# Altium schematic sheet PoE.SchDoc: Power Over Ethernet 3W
size A4; Date: 29-OCT-2015; Author: A.B; CompanyName: STMicroelectronics; Organization: MCD/TOOLS/GNB; Address1: 12, Rue Jules HOROWITZ; Address2: 38019 Grenoble; Address3: FRANCE; DocumentNumber: MB1225; Revision: B-01; SheetNumber: 11; SheetTotal: 13; Project: STM32F769I-DISCO
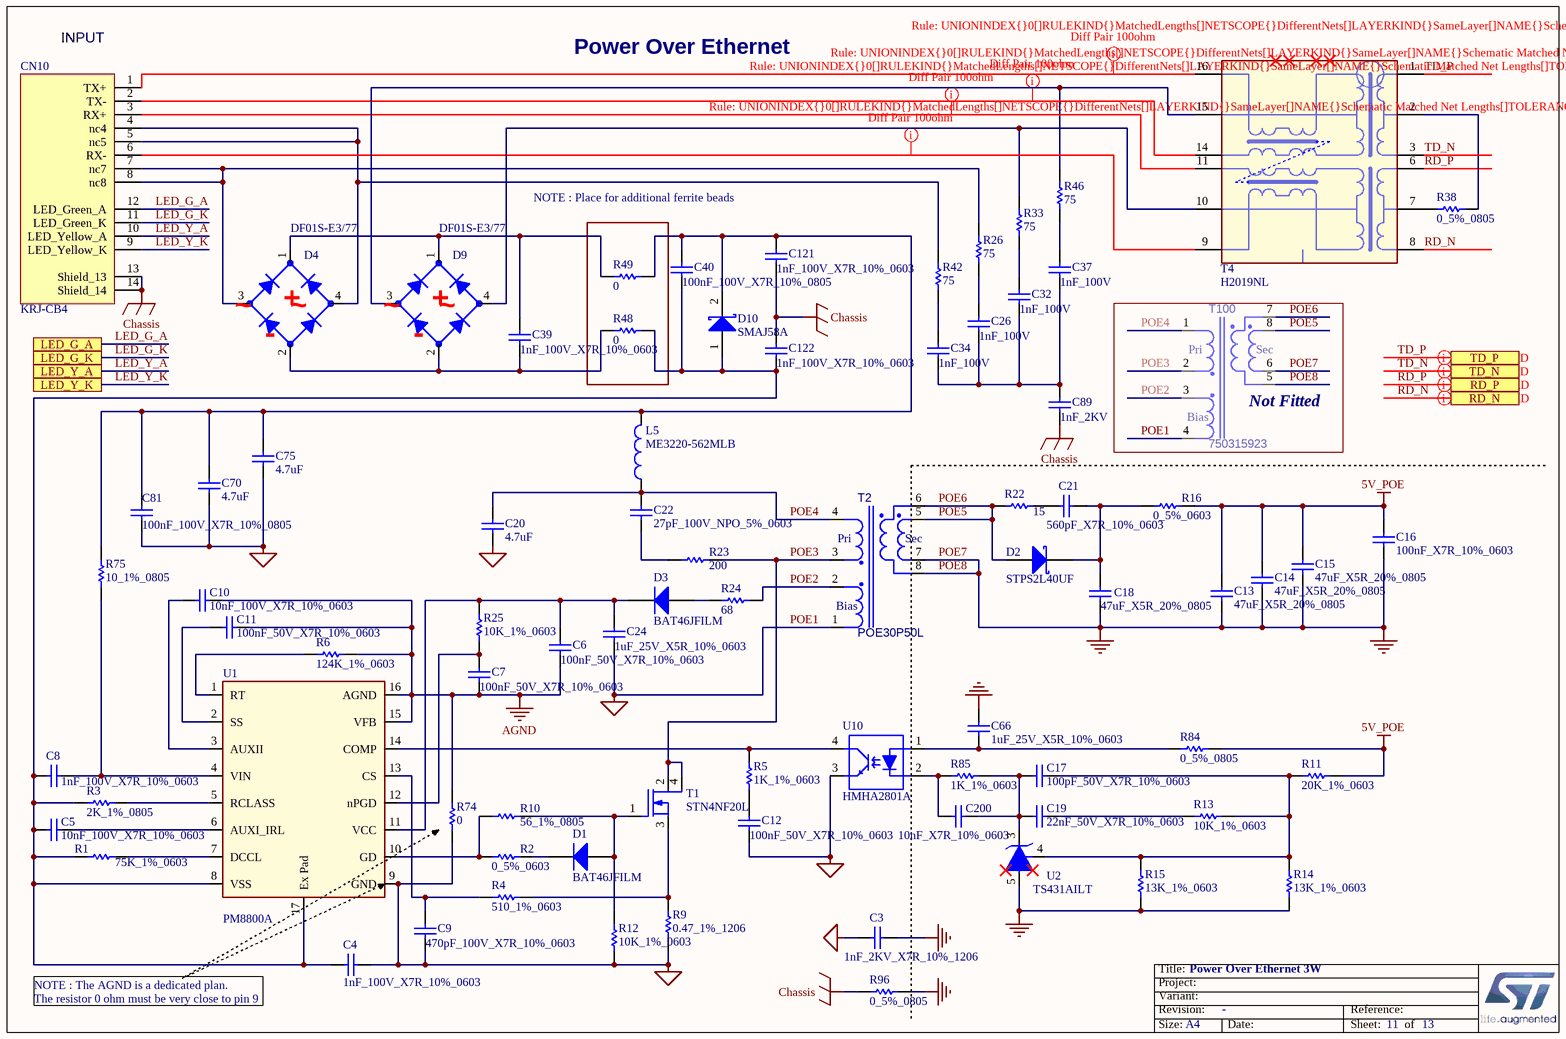
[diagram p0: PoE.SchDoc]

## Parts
C3  1nF_2KV_X7R_10%_1206  [1206C]
C4  1nF_100V_X7R_10%_0603  [0603C]
C5  10nF_100V_X7R_10%_0603  [0603C]
C6  100nF_50V_X7R_10%_0603  [0603C]
C7  100nF_50V_X7R_10%_0603  [0603C]
C8  1nF_100V_X7R_10%_0603  [0603C]
C9  470pF_100V_X7R_10%_0603  [0603C]
C10  10nF_100V_X7R_10%_0603  [0603C]
C11  100nF_50V_X7R_10%_0603  [0603C]
C12  100nF_50V_X7R_10%_0603  [0603C]
C13  47uF_X5R_20%_0805  [0805C]
C14  47uF_X5R_20%_0805  [0805C]
C15  47uF_X5R_20%_0805  [0805C]
C16  100nF_X7R_10%_0603  [0603C]
C17  100pF_50V_X7R_10%_0603  [0603C]
C18  47uF_X5R_20%_0805  [0805C]
C19  22nF_50V_X7R_10%_0603  [0603C]
C20  value 4.7uF  [C1210_H2P5]  (hidden comment: Capacitor)
C21  560pF_X7R_10%_0603  [0603C]
C22  27pF_100V_NPO_5%_0603  [0603C]
C24  1uF_25V_X5R_10%_0603  [0603C]
C26  1nF_100V  [0603C]
C32  1nF_100V  [0603C]
C34  1nF_100V  [0603C]
C37  1nF_100V  [0603C]
C39  1nF_100V_X7R_10%_0603  [0603C]
C40  100nF_100V_X7R_10%_0805  [0805C]
C66  1uF_25V_X5R_10%_0603  [0603C]
C70  value 4.7uF  [C1210_H2P5]  (hidden comment: Capacitor)
C75  value 4.7uF  [C1210_H2P5]  (hidden comment: Capacitor)
C81  100nF_100V_X7R_10%_0805  [0805C]
C89  1nF_2KV  [1206C]
C121  1nF_100V_X7R_10%_0603  [0603C]
C122  1nF_100V_X7R_10%_0603  [0603C]
C200  10nF_X7R_10%_0603  [0603C]
CN10  KRJ-CB4  [RJ45_LED_KRJ-CB4R2GYZNL_EM]
D1  BAT46JFILM  [SOD-323]
D2  STPS2L40UF  [SMB]
D3  BAT46JFILM  [SOD-323]
D4  value DF01S-E3/77  [BRF_VISHAY_DFS_DF01S]
D9  value DF01S-E3/77  [BRF_VISHAY_DFS_DF01S]
D10  SMAJ58A  [SMA]
L5  ME3220-562MLB  [LSM2_3R2X2R8_H2]
R1  75K_1%_0603  [0603R]
R2  0_5%_0603  [0603R-GS]
R3  2K_1%_0805  [0805R]
R4  510_1%_0603  [0603R]
R5  1K_1%_0603  [0603R]
R6  124K_1%_0603  [0603R]
R9  0.47_1%_1206  [1206R]
R10  56_1%_0805  [0805R]
R11  20K_1%_0603  [0603R]
R12  10K_1%_0603  [0603R]
R13  10K_1%_0603  [0603R]
R14  13K_1%_0603  [0603R]
R15  13K_1%_0603  [0603R]
R16  0_5%_0603  [0603R-GS]
R22  15  [0805R]
R23  200  [1206R]
R24  68  [0805R]
R25  10K_1%_0603  [0603R]
R26  75  [0805R]
R33  75  [0805R]
R38  0_5%_0805  [0805R]
R42  75  [0805R]
R46  75  [0805R]
R48  0  [0805R]
R49  0  [0805R]
R74  0  [0603R-GS]
R75  10_1%_0805  [0805R]
R84  0_5%_0805  [0805R]
R85  1K_1%_0603  [0603R]
R96  0_5%_0805  [0805R]
T1  STN4NF20L  [SOT-223]
T2  POE30P50L  [TF_10R9X13R2-12R2X14R4_CPT]
T4  H2019NL  [TF_16SM_12R7X9R65]
T100  750315923  [TF_8SM_12R04X12R85]
U1  PM8800A  [TSSOP16_0R65_5x6R4_TP]
U2  TS431AILT  [SOT23-5]
U10  HMHA2801A  [PC_4SM_1R27_2R5X6R8]

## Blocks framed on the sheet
Not Fitted: T100

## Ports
LED_G_A, LED_G_K, LED_Y_A, LED_Y_K, RD_N, RD_P, TD_N, TD_P

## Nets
5V_POE: C13.2 C14.2 C15.2 C16.2 R11.2 R16.2 R84.2
AGND: C6.1 C7.1 C10.2 C11.2 R6.2 R74.2 U1.15(VFB) U1.16(AGND)
Chassis: C89.1 C121.1 C122.2 CN10.13(Shield_13) CN10.14(Shield_14) R96.1
POE1: C3.1 C4.2 C9.1 C12.1 C20.1 C24.1 C70.1 C75.1 C81.1 R9.1 R12.1 R74.1 T2.1 T100.4 U1.9(GND) U10.3(Emitter)  [also labelled GND_POWER_IN]
POE7: C3.2 C13.1 C14.1 C15.1 C16.1 C18.1 C66.2 R14.1 R15.1 R96.2 T2.7 T2.8 T100.5 T100.6 U2.5(A)  [also labelled GND, POE8]
LED_G_A: CN10.12(LED_Green_A) ; port LED_G_A
LED_G_K: CN10.11(LED_Green_K) ; port LED_G_K
LED_Y_A: CN10.10(LED_Yellow_A) ; port LED_Y_A
LED_Y_K: CN10.9(LED_Yellow_K) ; port LED_Y_K
POE2: R24.2 T2.2 T100.3
POE3: R23.2 T1.2(D) T1.4(D) T2.3 T100.2
POE4: C20.2 C22.2 L5.1 T2.4 T100.1
POE5: D2.1(A) R22.1 T2.5 T2.6 T100.7 T100.8  [also labelled POE6]
RD_N: T4.8(rd-) ; port RD_N
RD_P: T4.6(rd+) ; port RD_P
TD_N: T4.3(td-) ; port TD_N
TD_P: T4.1(td+) ; port TD_P
NetC4_1: C4.1 C5.1 C8.1 C40.1 C122.1 D10.1(A) R1.1 R3.1 R48.2 U1.8(VSS) U1.17(Ex_Pad)
NetC5_2: C5.2 U1.6(AUXI_IRL)
NetC6_2: C6.2 C24.2 D3.2(K) R25.2 U1.11(VCC)
NetC7_2: C7.2 R25.1 U1.12(nPGD)
NetC8_2: C8.2 R75.1 U1.4(VIN)
NetC9_2: C9.2 R4.1 U1.13(CS)
NetC10_1: C10.1 U1.3(AUXII)
NetC11_1: C11.1 U1.2(SS)
NetC12_2: C12.2 R5.1
NetC17_1: C17.1 C19.1 C200.2 R85.2 U2.3(K)
NetC17_2: C17.2 R11.1 R13.2 R14.2 R15.2 U2.4(REF)
NetC18_2: C18.2 C21.2 D2.2(K) R16.1
NetC19_2: C19.2 R13.1
NetC21_1: C21.1 R22.2
NetC22_1: C22.1 R23.1
NetC26_1: C26.1 C32.1 C34.1 C37.1 C89.2
NetC26_2: C26.2 R26.1
NetC32_2: C32.2 R33.1
NetC34_2: C34.2 R42.1
NetC37_2: C37.2 R46.1
NetC39_1: C39.1 D4.2(DC_OUT_MINUS) D9.2(DC_OUT_MINUS) R48.1
NetC39_2: C39.2 D4.1(DC_OUT_PLUS) D9.1(DC_OUT_PLUS) R49.1
NetC40_2: C40.2 C70.2 C75.2 C81.2 C121.2 D10.2(K) L5.2 R49.2 R75.2
NetC66_1: C66.1 R84.1 U10.1(Anode)
NetC200_1: C200.1 R85.1 U10.2(B)
NetCN10_1: CN10.1(TX+) T4.16(tx1+)
NetCN10_2: CN10.2(TX-) T4.14(tx1-)
NetCN10_3: CN10.3(RX+) T4.11(rx1+)
NetCN10_4: CN10.4(nc4) CN10.5(nc5) D4.4(AC_IN_1) R42.2
NetCN10_6: CN10.6(RX-) T4.9(rx-)
NetCN10_7: CN10.7(nc7) CN10.8(nc8) D4.3(AC_IN_2) R26.2
NetD1_1: D1.1(A) R10.2 R12.2 T1.1(G)
NetD1_2: D1.2(K) R2.2
NetD3_1: D3.1(A) R24.1
NetD9_3: D9.3(AC_IN_2) R46.2 T4.15(txct)
NetD9_4: D9.4(AC_IN_1) R33.2 T4.10(rxct)
NetR1_2: R1.2 U1.7(DCCL)
NetR2_1: R2.1 R10.1 U1.10(GD)
NetR3_2: R3.2 U1.5(RCLASS)
NetR4_2: R4.2 R9.2 T1.3(S)
NetR5_2: R5.2 U1.14(COMP) U10.4(Collector)
NetR6_1: R6.1 U1.1(RT)
NetR38_1: R38.1 T4.7(rct)
NetR38_2: R38.2 T4.2(tct)

Not connected (* = marked no-connect by the designer): T4 4(nc_4)* 5(nc_5)* 12(nc_12)* 13(nc_13)*; U2 1(nc_1)* 2(nc_2)*

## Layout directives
differential pair: RD_N, RD_P, TD_N, TD_P
rule Matched Net Lengths [Tolerance = 100mil]: NetCN10_1, NetCN10_2, NetCN10_3, NetCN10_6

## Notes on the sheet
- (near CN10) INPUT
- Power Over Ethernet
- NOTE : Place for additional ferrite beads
- NOTE : The AGND is a dedicated plan.
  The resistor 0 ohm must be very close to pin 9

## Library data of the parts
C3 C89 = Cap_1nF_2KV_X7R_10%_1206: Capacitor,1nF,2KV,X7R,10%,1206,YAGEO; Order: CC1206KKX7RDBB102
C4 C8 C26 C32 C34 C37 C39 C121 C122 = Cap_1nF_100V_X7R_10%_0603: Capacitor,1nF,100V,X7R,10%,0603,YAGEO; Order: CC0603KRX7R0BB102
C5 C10 = Cap_10nF_100V_X7R_10%_0603: Capacitor,10nF,100V,X7R,10%,0603,YAGEO; Manuf_Part_1: CC0603KRX7R0BB103
C6 C7 C11 C12 = Cap_100nF_50V_X7R_10%_0603: Capacitor,100nF,50V,X7R,10%,0603,YAGEO; Manuf_Part_1: CC0603KRX7R9BB104
C9 = Cap_470pF_100V_X7R_10%_0603: Capacitor,470pF,100V,X7R,10%,0603,AVX; Manuf_Part_1: 06031C471KAT2A
C13-C15 C18 = Cap_47uF_X5R_20%_0805: Capacitor,47uF,10V,X5R,20%,0805,MURATA; Manuf_Part_1: GRM21BR61A476ME15K; Order: GRM21BR61A476ME15K-ND
C16 = Cap_100nF_X7R_10%_0603: Capacitor,100nF,16V,X7R,10%,0603,YAGEO; Manuf_Part_1: CC0603KRX7R9BB104
C17 = Cap_100pF_50V_X7R_10%_0603: Capacitor,100pF,50V,X7R,10%,0603,AVX; Manuf_Part_1: 06035C101JAT4A
C19 = Cap_22nF_50V_X7R_10%_0603: Capacitor,22nF,50V,X7R,10%,0603,YAGEO; Manuf_Part_1: CC0603KRX7R9BB223
C20 C70 C75 = MCD-02212: Capacitor, MLCC, 4.7uF, 100V, X7S, +/-10%, 1210 , T=2.5mm; Part_Preference: Recommended; Manufacturer: TDK; Manufacturer_Part_Number: CGA6M3X7S2A475K200AB; Order_Code_RS: 111-0119
C21 = Cap_560pF_X7R_10%_0603: Capacitor,560pF,16V,X7R,10%,0603,AVX; Manuf_Part_1: 0603YC561KAT2A
C22 = Cap_27pF_100V_NPO_5%_0603: Capacitor,27pF,100V,NPO,5%,0603,YAGEO; Manuf_Part_1: CC0603JRNPO0BN270; Manuf_2: AVX; Manuf_Part_2: 06031A270JAT2A; Fitted: NO
C24 C66 = Cap_1uF_25V_X5R_10%_0603: Capacitor,1uF,25V,X5R,10%,0603,YAGEO; Manuf_Part_1: CC0603KRX5R8BB105
C40 C81 = Cap_100nF_100V_X7R_10%_0805: Capacitor,100nF,100V,X7R,10%,0805,TDK; Order: C2012X7R2A104K125AA
C200 = Cap_10nF_X7R_10%_0603: Capacitor,10nF,50V,X7R,10%,0603,YAGEO; Manuf_Part_1: CC0603KRX7R9BB103
CN10 = KRJ-CB4: 100 Base-TX (Fast Ethernet)  RJ45 single port (1x1) with LEDS Integrated Connector; Manuf_1: DGKYD; Manuf_Part_1: KRJ-CB4.2GYZNL
D1 D3 = BAT46JFILM: Schottky Single diode(150mA, 100V); Manuf_1: STM; Provided: ST; ECCN_US/EU: EAR99/NEC; Ref St: 9151125
D2 = STPS2L40UF: Low drop power Schottky rectifier(2A, 40V, 0.34V); Manuf_1: STM; Order: STPS2L40AF; Provided: ST; ECCN_US/EU: EAR99/NEC; Code - JEDEC: ******; Note: SMB footprint will accept STPS2L40U/UF/AF; Ref St: 9151009
D4 D9 = MCD-02211: Surface Mount Bridge Rectifier 1A 100V; Part_Preference: Recommended; Part_Type: IC; Manufacturer: VISHAY
D10 = SMAJ58A: Transil 400W, VRM=58V; Manuf_1: STM; Manuf_Part_1: SMAJ58A-TR; ECCN_US/EU: EAR99/NEC; Provided: ST; Ref St: 9151124
L5 = ME3220-562ML: Power Inductor, 5.6uH, 0.2R, ME3220-562ML, CoilCraft; Manuf_2: Cyntec; Manuf_Part_2: SDET32251E-5R6MS-11
R1 = Res_75K_1%_0603: Resistor,75K,0603,1%,YAGEO; Manuf_Part_1: RC0603FR-0775KL
R2 R16 = Res_0_5%_0603: Resistor,0,0603,5%,YAGEO; Manuf_Part_1: RC0603JR-070RL; Value: 0; Order: 2363481
R3 = Res_2K_1%_0805: Resistor,2K,0805,1%,YAGEO; Manuf_Part_1: RC0805FR-072KL; Manuf_Part_2: RT0805FRE072KL
R4 = Res_510_1%_0603: Resistor,510,0603,1%,YAGEO; Manuf_Part_1: RC0603FR-07510RL; Value: 510
R5 R85 = Res_1K_1%_0603: Resistor,1K,0603,1%,YAGEO; Manuf_Part_1: RC0603FR-071KL
R6 = Res_124K_1%_0603: Resistor,124K,0603,1%,YAGEO; Manuf_Part_1: RC0603FR-07124KL
R9 = Res_0.47_1%_1206: Resistor,0.47,1206,1%,YAGEO; Manuf_Part_1: RL1206FR-070R47L; Manuf_Part_2: LTR18EZPFLR470; Manuf_2: Rohm Semiconductor; Value: 0.47
R10 = Res_56_1%_0805: Resistor,56,0805,1%,YAGEO; Manuf_Part_1: RC0805FR-0756RL; Value: 56; Order: 311-56.0CRTR-ND
R11 = Res_20K_1%_0603: Resistor,20K,0603,1%,YAGEO; Manuf_Part_1: RC0603FR-0720KL
R12 R13 R25 = Res_10K_1%_0603: Resistor,10K,0603,1%,YAGEO; Manuf_Part_1: RC0603FR-0710KL
R14 R15 = Res_13K_1%_0603: Resistor,13K,0603,1%,YAGEO; Manuf_Part_1: RC0603FR-0713KL
R22 = Res_15_1%_0805: Resistor,15,0805,1%,YAGEO; Manuf_Part_1: RC0805FR-0715RL
R23 = Res_200_1%_1206: Resistor,200,1206,1%,Rohm; Manuf_Part_1: LTR18EZPF2000; Manuf_1: Rohm Semiconductor; Fitted: NO
R24 = Res_68_1%_0805: Resistor,68,0805,1%,YAGEO; Manuf_Part_1: RC0805FR-0768RL
R26 R33 R42 R46 = Res_75_1%_0805: Resistor,75,0805,1%,YAGEO; Manuf_Part_1: RC0805FR-0775RL; Order: 311-75.0CRTR-ND
R38 = Res_0_5%_0805: Resistor,0,0805,5%,YAGEO; Manuf_Part_1: RC0805JR-070RL; Value: 0; Order: 2363489; Fitted: NO
R48 R49 = Res_0_5%_0805: Resistor,0,0805,5%,YAGEO; Manuf_Part_1: RC0805JR-070RL; Order: 2363489
R74 = Res_0_5%_0603: Resistor,0,0603,5%,YAGEO; Manuf_Part_1: RC0603JR-070RL; Order: 2363481
R75 = Res_10_1%_0805: Resistor,10,0805,1%,Stackpole,1/4W; Manuf_Part_1: RNCP0805FTD10R0; Manuf_1: Stackpole Electronics Inc; Value: 10
R84 R96 = Res_0_5%_0805: Resistor,0,0805,5%,YAGEO; Manuf_Part_1: RC0805JR-070RL; Value: 0; Order: 2363489
T1 = STN4NF20L: N-channel 200 V, 1.1ohm, 1 A, low gate charge STripFET II, Power MOSFET; Manuf_2: Fairchild; Manuf_Part_2: FDN86246; Manuf_1: ST; ECCN_US/EU: EAR99/NEC; Ref St: 9153018
T2 = POE30P_C: Flyback Transformers for 3 Watt, PoE applications, CoilCraft Cyntec; Manuf_Part_1: POEP30P50L; Manuf_Part_2: 86H-15181; Provided: Sub Co; Note: for Cyntec, Secondary 6, 7 removed
T4 = H2019: 10/100BASE-TX VoIP Magnetics Modules, Data Transformer; Manuf_Part_2: TLA-6T127LF, with different pinout; Manuf_1: PULSE; Manuf_2: TDK; Manuf_Part_3: KMS-1102NL; Manuf_3: DGKYD; Double foot print: TLA-6T127LF, pin 10, 12, 13, 15 differents; ECCN_US/EU: EAR99/NEC
T100 = POE30P_W: Flyback Transformers for 3 Watt, PoE applications, Wurth; Provided: Sub Co; Note: Compatible with CoilCraft but swap pins 1 and 4, pins 2 and 3, pins 5 and 8, pins 6 and 7; Fitted: NO
U1 = PM8800A: Integrated IEEE 802.3af compliant PoE-PD interface, and PWM controller with support of external source; Manuf_Part_1: PM8800ATR; Manuf_1: ST; Provided: STM; ECCN_US/EU: EAR99/NEC; Ref St: 9177966
U2 = TS431AILT: Low voltage adjustable shunt reference; Manuf_1: ST; ECCN_US/EU: EAER99/NEC; Ref St: 9177032
U10 = HMHA2801A: OPTOISOLATOR 3.7KV TRANSISTOR 4SMD; Manuf_1: FAIRCHILD; Order: HMHA2801A-ND; ECCN_US/EU: EAR99/NEC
